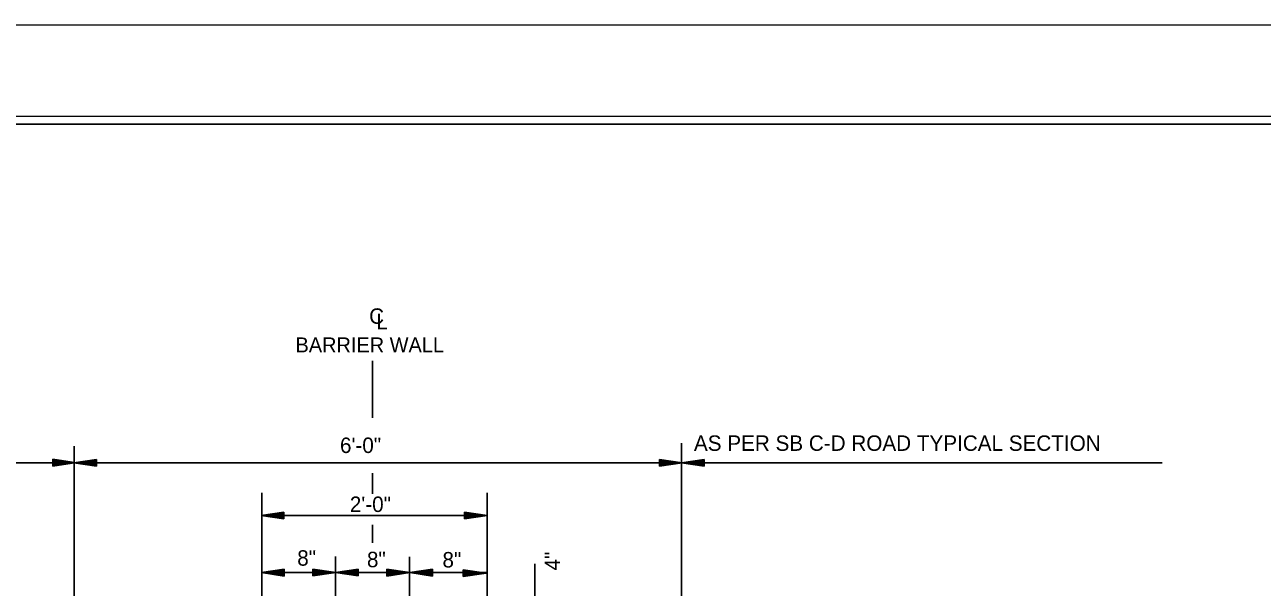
# Model space of a CAD drawing. Extents: x 714919 to 718439, y 1619644 to 1621844.
# Drawn here: x 715497 to 716327, y 1621466 to 1621844 of the extents above; entities that cross this region are included whole.
import ezdxf

# ---------------------------------------------------------------- set-up
doc = ezdxf.new("R2010")
doc.units = 0
for name, color, linetype in [('R_Border', 7, 'Continuous'), ('R_Centerline', 7, 'Continuous'), ('R_Dimension', 7, 'Continuous'), ('R_No Plot', 7, 'Continuous')]:
    doc.layers.add(name, color=color, linetype=linetype)

msp = doc.modelspace()

# ---------------------------------------------------------------- linework, layer by layer
at = {"layer": 'R_Border'}
for p, q in [((718438.81, 1621843.86), (714918.81, 1621843.65)), ((715231.11, 1621777.16), (718392.91, 1621777.16))]:
    msp.add_line(p, q, dxfattribs=at)
at = {"layer": 'R_Centerline'}
for p, q in [((715730.33, 1621618.48), (715730.33, 1621580.12)), ((715730.33, 1621542.97), (715730.33, 1621529.14)), ((715730.36, 1621508.24), (715730.36, 1621496.32))]:
    msp.add_line(p, q, dxfattribs=at)
at = {"layer": 'R_Dimension'}
for p, q in [((715937.5, 1621563.18), (715937.5, 1621274.43)), ((715530.22, 1621561.2), (715530.22, 1621352.71)), ((715276.82, 1621549.97), (715530.54, 1621549.97)), ((715516.03, 1621552.3), (715530.54, 1621550.1)), ((715516.03, 1621552.3), (715516.03, 1621547.72)), ((715516.03, 1621551.96), (715528.82, 1621549.97)), ((715516.03, 1621551.53), (715526.14, 1621549.97)), ((715516.03, 1621551.18), (715523.63, 1621549.97)), ((715516.03, 1621550.75), (715521.04, 1621549.97)), ((715516.03, 1621550.4), (715518.53, 1621549.97)), ((715516.03, 1621549.28), (715521.04, 1621549.97)), ((715516.03, 1621548.5), (715526.14, 1621549.97)), ((715516.03, 1621548.07), (715528.82, 1621549.97)), ((715516.03, 1621548.85), (715523.63, 1621549.97)), ((715516.03, 1621549.62), (715518.53, 1621549.97)), ((715516.03, 1621547.72), (715530.54, 1621549.84)), ((715545.15, 1621552.21), (715529.95, 1621549.93)), ((715545.15, 1621547.65), (715529.95, 1621549.93)), ((715530.22, 1621549.97), (715730.36, 1621549.97)), ((715545.15, 1621551.83), (715532.49, 1621549.93)), ((715545.15, 1621548.03), (715532.49, 1621549.93)), ((715545.15, 1621551.44), (715535.1, 1621549.93)), ((715545.15, 1621548.42), (715535.1, 1621549.93)), ((715545.15, 1621551.06), (715537.63, 1621549.93)), ((715545.15, 1621548.8), (715537.63, 1621549.93)), ((715545.15, 1621550.67), (715540.21, 1621549.93)), ((715545.15, 1621549.19), (715540.21, 1621549.93)), ((715545.15, 1621550.29), (715542.74, 1621549.93)), ((715545.15, 1621549.58), (715542.74, 1621549.93)), ((715545.15, 1621552.21), (715545.15, 1621547.65)), ((715730.36, 1621549.97), (715937.5, 1621549.97)), ((715922.68, 1621552.25), (715937.88, 1621549.97)), ((715922.68, 1621552.25), (715922.68, 1621547.69)), ((715922.68, 1621551.87), (715935.34, 1621549.97)), ((715922.68, 1621551.48), (715932.73, 1621549.97)), ((715922.68, 1621551.1), (715930.2, 1621549.97)), ((715922.68, 1621550.71), (715927.62, 1621549.97)), ((715922.68, 1621550.33), (715925.09, 1621549.97)), ((715922.68, 1621547.69), (715937.88, 1621549.97)), ((715922.68, 1621549.23), (715927.62, 1621549.97)), ((715922.68, 1621548.46), (715932.73, 1621549.97)), ((715922.68, 1621548.07), (715935.34, 1621549.97)), ((715922.68, 1621548.84), (715930.2, 1621549.97)), ((715922.68, 1621549.62), (715925.09, 1621549.97)), ((715952.7, 1621552.25), (715937.5, 1621549.97)), ((715937.5, 1621549.97), (716259.81, 1621549.97)), ((715952.7, 1621547.69), (715937.5, 1621549.97)), ((715952.7, 1621551.87), (715940.04, 1621549.97)), ((715952.7, 1621548.07), (715940.04, 1621549.97)), ((715952.7, 1621551.48), (715942.65, 1621549.97)), ((715952.7, 1621548.46), (715942.65, 1621549.97)), ((715952.7, 1621551.1), (715945.18, 1621549.97)), ((715952.7, 1621548.84), (715945.18, 1621549.97)), ((715952.7, 1621550.71), (715947.76, 1621549.97)), ((715952.7, 1621549.23), (715947.76, 1621549.97)), ((715952.7, 1621550.33), (715950.29, 1621549.97)), ((715952.7, 1621549.62), (715950.29, 1621549.97)), ((715952.7, 1621552.25), (715952.7, 1621547.69)), ((715656.14, 1621529.75), (715656.14, 1621193.74)), ((715807.25, 1621529.75), (715807.25, 1621193.74)), ((715670.92, 1621516.88), (715655.54, 1621514.55)), ((715670.92, 1621512.3), (715655.54, 1621514.55)), ((715656.14, 1621514.55), (715807.25, 1621514.55)), ((715670.92, 1621516.53), (715658.04, 1621514.55)), ((715670.92, 1621512.65), (715658.04, 1621514.55)), ((715670.92, 1621516.1), (715660.81, 1621514.55)), ((715670.92, 1621513.08), (715660.81, 1621514.55)), ((715670.92, 1621515.76), (715663.31, 1621514.55)), ((715670.92, 1621513.42), (715663.31, 1621514.55)), ((715670.92, 1621515.32), (715665.9, 1621514.55)), ((715670.92, 1621513.85), (715665.9, 1621514.55)), ((715670.92, 1621514.98), (715668.41, 1621514.55)), ((715670.92, 1621514.2), (715668.41, 1621514.55)), ((715670.92, 1621512.3), (715670.92, 1621516.88)), ((715791.88, 1621516.88), (715807.25, 1621514.55)), ((715791.88, 1621516.88), (715791.88, 1621512.3)), ((715791.88, 1621516.53), (715804.66, 1621514.55)), ((715791.88, 1621516.1), (715801.98, 1621514.55)), ((715791.88, 1621515.76), (715799.48, 1621514.55)), ((715791.88, 1621515.32), (715796.89, 1621514.55)), ((715791.88, 1621514.98), (715794.38, 1621514.55)), ((715791.88, 1621512.3), (715807.25, 1621514.55)), ((715791.88, 1621513.85), (715796.89, 1621514.55)), ((715791.88, 1621513.08), (715801.98, 1621514.55)), ((715791.88, 1621512.65), (715804.66, 1621514.55)), ((715791.88, 1621513.42), (715799.48, 1621514.55)), ((715791.88, 1621514.2), (715794.38, 1621514.55)), ((715705.56, 1621487.07), (715705.56, 1621446.55)), ((715754.98, 1621486.9), (715754.98, 1621446.38)), ((715839.22, 1621482.23), (715839.22, 1621437.91)), ((715671.09, 1621478.52), (715655.8, 1621476.27)), ((715671.09, 1621473.94), (715655.8, 1621476.27)), ((715656.14, 1621476.27), (715711.18, 1621476.27)), ((715671.09, 1621478.17), (715658.3, 1621476.27)), ((715671.09, 1621474.28), (715658.3, 1621476.27)), ((715671.09, 1621477.74), (715660.98, 1621476.27)), ((715671.09, 1621474.72), (715660.98, 1621476.27)), ((715671.09, 1621477.39), (715663.49, 1621476.27)), ((715671.09, 1621475.06), (715663.49, 1621476.27)), ((715671.09, 1621477.05), (715666.16, 1621476.27)), ((715671.09, 1621475.49), (715666.16, 1621476.27)), ((715671.09, 1621476.62), (715668.67, 1621476.27)), ((715671.09, 1621475.84), (715668.67, 1621476.27)), ((715671.09, 1621473.94), (715671.09, 1621478.52)), ((715690.27, 1621478.69), (715705.65, 1621476.36)), ((715690.27, 1621478.69), (715690.27, 1621474.11)), ((715690.27, 1621478.26), (715703.14, 1621476.36)), ((715690.27, 1621477.91), (715700.38, 1621476.36)), ((715690.27, 1621477.57), (715697.87, 1621476.36)), ((715690.27, 1621477.13), (715695.28, 1621476.36)), ((715690.27, 1621476.79), (715692.77, 1621476.36)), ((715690.27, 1621474.11), (715705.65, 1621476.36)), ((715690.27, 1621475.58), (715695.28, 1621476.36)), ((715690.27, 1621474.8), (715700.38, 1621476.36)), ((715690.27, 1621474.46), (715703.14, 1621476.36)), ((715690.27, 1621475.23), (715697.87, 1621476.36)), ((715690.27, 1621476.01), (715692.77, 1621476.36)), ((715720.77, 1621478.69), (715705.39, 1621476.36)), ((715720.77, 1621474.11), (715705.39, 1621476.36)), ((715720.77, 1621478.26), (715707.89, 1621476.36)), ((715720.77, 1621474.46), (715707.89, 1621476.36)), ((715720.77, 1621477.91), (715710.66, 1621476.36)), ((715720.77, 1621474.8), (715710.66, 1621476.36)), ((715711.18, 1621476.27), (715749.45, 1621476.27)), ((715720.77, 1621477.57), (715713.17, 1621476.36)), ((715720.77, 1621475.23), (715713.17, 1621476.36)), ((715720.77, 1621477.13), (715715.76, 1621476.36)), ((715720.77, 1621475.58), (715715.76, 1621476.36)), ((715720.77, 1621476.79), (715718.26, 1621476.36)), ((715720.77, 1621476.01), (715718.26, 1621476.36)), ((715720.77, 1621474.11), (715720.77, 1621478.69)), ((715739.95, 1621478.52), (715755.33, 1621476.27)), ((715739.95, 1621478.52), (715739.95, 1621473.94)), ((715739.95, 1621478.17), (715752.82, 1621476.27)), ((715739.95, 1621477.74), (715750.06, 1621476.27)), ((715739.95, 1621477.39), (715747.55, 1621476.27)), ((715739.95, 1621477.05), (715744.96, 1621476.27)), ((715739.95, 1621476.62), (715742.45, 1621476.27)), ((715739.95, 1621473.94), (715755.33, 1621476.27)), ((715739.95, 1621475.49), (715744.96, 1621476.27)), ((715739.95, 1621474.72), (715750.06, 1621476.27)), ((715739.95, 1621474.28), (715752.82, 1621476.27)), ((715739.95, 1621475.06), (715747.55, 1621476.27)), ((715739.95, 1621475.84), (715742.45, 1621476.27)), ((715754.98, 1621476.27), (715807.25, 1621476.27)), ((715770.62, 1621478.6), (715755.24, 1621476.27)), ((715770.62, 1621474.02), (715755.24, 1621476.27)), ((715770.62, 1621478.26), (715757.75, 1621476.27)), ((715770.62, 1621474.37), (715757.75, 1621476.27)), ((715770.62, 1621477.83), (715760.43, 1621476.27)), ((715770.62, 1621474.8), (715760.43, 1621476.27)), ((715770.62, 1621477.48), (715763.02, 1621476.27)), ((715770.62, 1621475.15), (715763.02, 1621476.27)), ((715770.62, 1621477.05), (715765.61, 1621476.27)), ((715770.62, 1621475.49), (715765.61, 1621476.27)), ((715770.62, 1621476.7), (715768.12, 1621476.27)), ((715770.62, 1621475.93), (715768.12, 1621476.27)), ((715770.62, 1621474.02), (715770.62, 1621478.6)), ((715791.01, 1621478.26), (715806.39, 1621475.93)), ((715791.01, 1621478.26), (715791.01, 1621473.59)), ((715791.01, 1621477.83), (715803.89, 1621475.93)), ((715791.01, 1621477.48), (715801.12, 1621475.93)), ((715791.01, 1621477.05), (715798.61, 1621475.93)), ((715791.01, 1621476.7), (715796.02, 1621475.93)), ((715791.01, 1621476.27), (715793.52, 1621475.93)), ((715791.01, 1621473.59), (715806.39, 1621475.93)), ((715791.01, 1621475.15), (715796.02, 1621475.93)), ((715791.01, 1621474.37), (715801.12, 1621475.93)), ((715791.01, 1621474.02), (715803.89, 1621475.93)), ((715791.01, 1621474.8), (715798.61, 1621475.93)), ((715791.01, 1621475.49), (715793.52, 1621475.93))]:
    msp.add_line(p, q, dxfattribs=at)
at = {"layer": 'R_No Plot'}
msp.add_lwpolyline([(715227.03, 1619717.36), (718396.93, 1619717.46), (718396.96, 1621782.56), (715226.86, 1621782.36)], close=True, dxfattribs=at)

# ---------------------------------------------------------------- texts
at = {"layer": 'R_Centerline'}
for s, height, p in [('C', 10.37, (715728.03, 1621643.2)), ('L', 10.37, (715732.78, 1621639.57)), ('BARRIER WALL', 10, (715678.65, 1621624.07))]:
    msp.add_text(s, height=height, dxfattribs=at).set_placement(p)
at = {"layer": 'R_Dimension'}
for s, height, p in [('6\'-0"', 10.369, (715708.47, 1621556.54)), ('AS PER SB C-D ROAD TYPICAL SECTION', 10.3685, (715945.82, 1621557.98)), ('2\'-0"', 10.369, (715715.07, 1621516.97)), ('8"', 10.369, (715679.81, 1621480.94)), ('8"', 10.369, (715726.56, 1621479.9)), ('8"', 10.369, (715777.19, 1621479.73))]:
    msp.add_text(s, height=height, dxfattribs=at).set_placement(p)
msp.add_text('4"', height=10.369, rotation=90, dxfattribs=at).set_placement((715856.07, 1621477.74))

doc.saveas('drawing.dxf')
